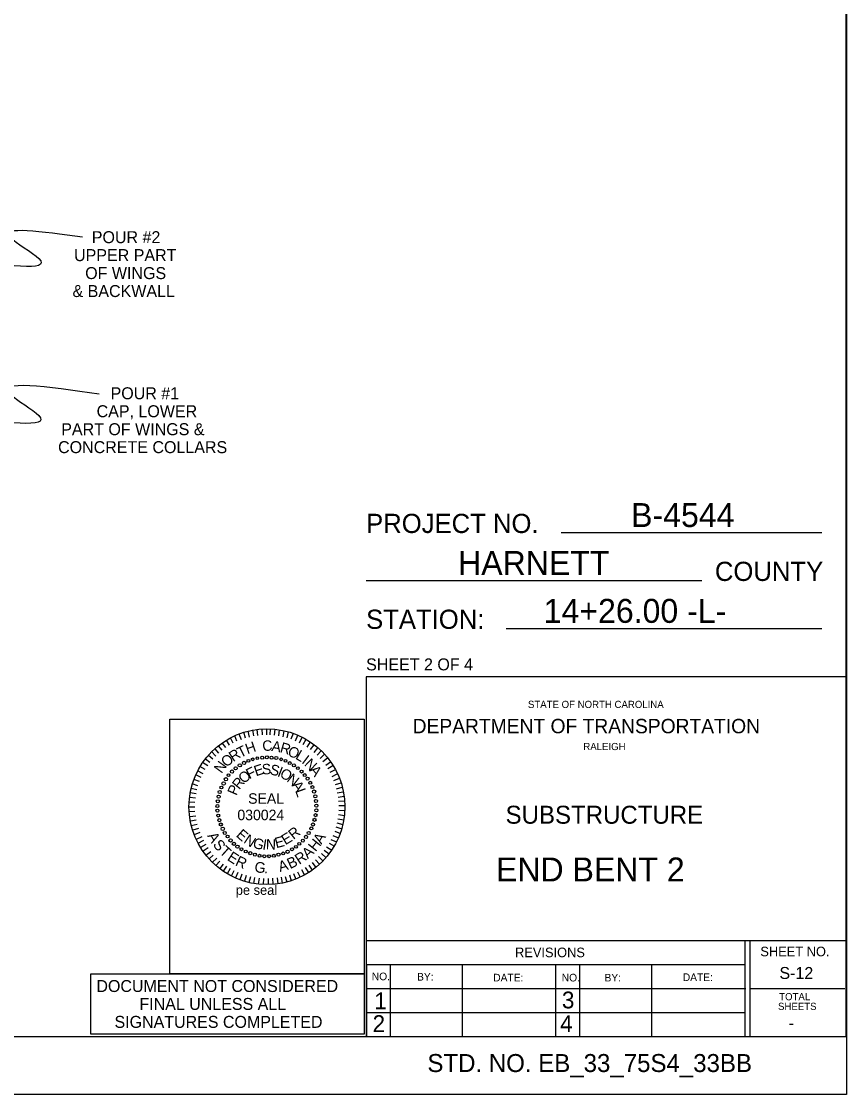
# Model space of a CAD drawing. Extents: x -41 to 191, y -168 to 6.
# Drawn here: x 171.73 to 191.43, y -50.47 to -24.84 of the extents above; entities that cross this region are included whole.
import ezdxf

# ---------------------------------------------------------------- set-up
doc = ezdxf.new("R2010")
doc.units = 0
for name, color, linetype in [('Dimension Lines', 7, 'Continuous'), ('Peseal', 7, 'Continuous'), ('Plan Sheet CELL', 7, 'Continuous'), ('Plot Shape CELL', 7, 'Continuous'), ('Sheet Sticker Exception Certification CELL', 7, 'Continuous'), ('Subtitle Text', 7, 'Continuous'), ('Text', 7, 'Continuous'), ('Title Text', 7, 'Continuous'), ('User Information Notes', 7, 'Continuous'), ('User Information Notes CELL', 7, 'Continuous')]:
    doc.layers.add(name, color=color, linetype=linetype)

msp = doc.modelspace()

# ---------------------------------------------------------------- linework, layer by layer
at = {"layer": 'Dimension Lines'}
for points in [[(173.186, -29.991), (171.467, -29.991), (172.144, -30.499), (170.147, -30.499)], [(173.587, -33.741), (171.467, -33.741), (172.144, -34.249), (170.147, -34.249)]]:
    msp.add_spline(points, degree=3, dxfattribs=at)
at = {"layer": 'Peseal'}
for p, q in [((177.277, -41.903), (177.251, -41.76)), ((177.376, -41.894), (177.358, -41.751)), ((177.483, -41.876), (177.474, -41.733)), ((177.591, -41.876), (177.591, -41.733)), ((177.671, -41.876), (177.68, -41.733)), ((177.769, -41.885), (177.787, -41.742)), ((177.877, -41.903), (177.895, -41.76)), ((176.696, -42.126), (176.624, -42.001)), ((176.785, -42.073), (176.723, -41.947)), ((176.875, -42.028), (176.821, -41.903)), ((176.982, -41.992), (176.929, -41.858)), ((177.081, -41.956), (177.036, -41.813)), ((177.179, -41.93), (177.143, -41.786)), ((177.975, -41.921), (178.002, -41.777)), ((178.074, -41.947), (178.109, -41.804)), ((178.172, -41.974), (178.226, -41.84)), ((178.27, -42.019), (178.333, -41.885)), ((178.369, -42.064), (178.431, -41.93)), ((178.458, -42.108), (178.53, -41.983)), ((176.374, -42.386), (176.267, -42.278)), ((176.446, -42.314), (176.356, -42.207)), ((176.526, -42.243), (176.437, -42.135)), ((176.607, -42.18), (176.526, -42.064)), ((178.548, -42.171), (178.628, -42.046)), ((178.628, -42.225), (178.718, -42.117)), ((178.718, -42.296), (178.807, -42.189)), ((178.789, -42.359), (178.888, -42.261)), ((176.177, -42.618), (176.052, -42.538)), ((176.231, -42.538), (176.124, -42.457)), ((176.302, -42.457), (176.195, -42.368)), ((178.861, -42.439), (178.968, -42.341)), ((178.923, -42.511), (179.04, -42.422)), ((178.995, -42.6), (179.111, -42.52)), ((176.07, -42.806), (175.936, -42.735)), ((176.115, -42.708), (175.989, -42.636)), ((179.049, -42.681), (179.165, -42.609)), ((179.102, -42.77), (179.228, -42.708)), ((175.945, -43.092), (175.81, -43.048)), ((175.98, -42.994), (175.846, -42.94)), ((176.025, -42.896), (175.891, -42.833)), ((179.147, -42.869), (179.272, -42.806)), ((179.192, -42.967), (179.326, -42.914)), ((179.228, -43.066), (179.362, -43.021)), ((175.9, -43.289), (175.757, -43.262)), ((175.918, -43.191), (175.784, -43.155)), ((179.254, -43.164), (179.389, -43.128)), ((179.272, -43.262), (179.415, -43.236)), ((175.873, -43.495), (175.73, -43.486)), ((175.882, -43.388), (175.748, -43.37)), ((179.29, -43.361), (179.433, -43.343)), ((179.299, -43.459), (179.442, -43.45)), ((175.873, -43.602), (175.73, -43.602)), ((175.873, -43.71), (175.73, -43.719)), ((175.891, -43.817), (175.748, -43.835)), ((179.299, -43.781), (179.442, -43.799)), ((179.308, -43.567), (179.451, -43.567)), ((179.308, -43.674), (179.451, -43.683)), ((175.9, -43.915), (175.766, -43.942)), ((175.927, -44.014), (175.784, -44.05)), ((179.236, -44.076), (179.38, -44.121)), ((179.263, -43.978), (179.406, -44.014)), ((179.281, -43.88), (179.424, -43.906)), ((175.954, -44.112), (175.819, -44.157)), ((175.989, -44.211), (175.855, -44.264)), ((176.034, -44.309), (175.9, -44.372)), ((179.165, -44.282), (179.299, -44.336)), ((179.21, -44.175), (179.344, -44.229)), ((176.079, -44.398), (175.945, -44.47)), ((176.132, -44.497), (176.007, -44.568)), ((176.186, -44.577), (176.07, -44.658)), ((179.013, -44.551), (179.138, -44.631)), ((179.075, -44.461), (179.201, -44.533)), ((179.12, -44.372), (179.254, -44.434)), ((176.249, -44.667), (176.132, -44.756)), ((176.311, -44.747), (176.213, -44.837)), ((176.392, -44.819), (176.285, -44.926)), ((178.825, -44.783), (178.932, -44.89)), ((178.897, -44.712), (179.004, -44.81)), ((178.959, -44.631), (179.075, -44.721)), ((176.463, -44.89), (176.374, -44.998)), ((176.544, -44.962), (176.463, -45.069)), ((176.624, -45.016), (176.544, -45.132)), ((176.714, -45.069), (176.642, -45.195)), ((178.414, -45.096), (178.485, -45.23)), ((178.503, -45.043), (178.583, -45.168)), ((178.592, -44.989), (178.673, -45.105)), ((178.673, -44.926), (178.762, -45.043)), ((178.753, -44.864), (178.843, -44.962)), ((176.803, -45.123), (176.741, -45.248)), ((176.893, -45.168), (176.839, -45.293)), ((176.991, -45.204), (176.946, -45.338)), ((177.099, -45.239), (177.054, -45.374)), ((177.197, -45.266), (177.161, -45.4)), ((177.295, -45.284), (177.269, -45.427)), ((177.403, -45.302), (177.385, -45.445)), ((177.51, -45.311), (177.501, -45.454)), ((177.617, -45.311), (177.617, -45.454)), ((177.725, -45.302), (177.734, -45.445)), ((177.832, -45.293), (177.85, -45.436)), ((177.93, -45.275), (177.957, -45.418)), ((178.029, -45.257), (178.065, -45.391)), ((178.127, -45.221), (178.172, -45.365)), ((178.226, -45.186), (178.279, -45.32)), ((178.324, -45.15), (178.387, -45.275))]:
    msp.add_line(p, q, dxfattribs=at)
for centre, radius in [((177.045, -42.547), 0.04), ((177.148, -42.498), 0.0341), ((177.251, -42.462), 0.0326), ((177.362, -42.435), 0.0316), ((177.479, -42.422), 0.0361), ((177.591, -42.413), 0.0358), ((177.702, -42.422), 0.0361), ((177.814, -42.431), 0.0369), ((177.93, -42.462), 0.0326), ((178.033, -42.498), 0.0341), ((178.136, -42.551), 0.0361), ((176.759, -42.753), 0.038), ((176.844, -42.677), 0.0385), ((176.942, -42.605), 0.0385), ((178.235, -42.605), 0.0361), ((178.329, -42.672), 0.0349), ((178.418, -42.753), 0.0349), ((176.557, -43.039), 0.0412), ((176.611, -42.936), 0.0385), ((176.674, -42.838), 0.0316), ((178.494, -42.838), 0.0349), ((178.561, -42.923), 0.0361), ((178.624, -43.021), 0.0361), ((176.463, -43.24), 0.0382), ((176.504, -43.133), 0.0341), ((178.677, -43.124), 0.0341), ((178.718, -43.231), 0.0382), ((178.745, -43.343), 0.0369), ((176.41, -43.576), 0.0358), ((176.419, -43.464), 0.0361), ((176.437, -43.352), 0.0369), ((178.762, -43.455), 0.0361), ((178.771, -43.567), 0.0358), ((176.41, -43.687), 0.0361), ((176.428, -43.804), 0.0361), ((178.753, -43.795), 0.0361), ((178.771, -43.678), 0.0361), ((176.454, -43.915), 0.0369), ((176.49, -44.018), 0.0382), ((178.651, -44.112), 0.0361), ((178.691, -44.018), 0.0382), ((178.727, -43.906), 0.0369), ((176.535, -44.121), 0.04), ((176.584, -44.22), 0.0361), ((176.651, -44.305), 0.0349), ((178.525, -44.314), 0.0385), ((178.588, -44.22), 0.0361), ((176.723, -44.398), 0.038), ((176.803, -44.479), 0.038), ((176.888, -44.546), 0.0385), ((176.982, -44.609), 0.0361), ((178.19, -44.609), 0.0361), ((178.284, -44.551), 0.0349), ((178.364, -44.479), 0.0349), ((178.449, -44.403), 0.0349), ((177.085, -44.662), 0.0341), ((177.192, -44.703), 0.0382), ((177.304, -44.738), 0.0369), ((177.416, -44.765), 0.0361), ((177.528, -44.774), 0.0358), ((177.644, -44.774), 0.0358), ((177.756, -44.765), 0.0361), ((177.868, -44.738), 0.0369), ((177.98, -44.707), 0.0341), ((178.083, -44.667), 0.04)]:
    msp.add_circle(centre, radius, dxfattribs=at)
at = {"layer": 'Plan Sheet CELL'}
for p, q in [((191.409, -0.989), (191.409, -49.079)), ((190.837, -37.056), (184.615, -37.056)), ((187.974, -38.201), (179.959, -38.201)), ((190.837, -39.345), (183.303, -39.345)), ((191.409, -40.49), (179.959, -40.49)), ((179.959, -40.49), (179.959, -49.079)), ((179.959, -46.788), (191.409, -46.788)), ((189.005, -46.788), (189.005, -49.079)), ((189.12, -46.788), (189.12, -49.079)), ((179.959, -47.36), (189.01, -47.36)), ((179.966, -47.36), (179.966, -49.079)), ((180.531, -47.36), (180.531, -49.079)), ((182.249, -47.37), (182.249, -49.087)), ((184.484, -47.36), (184.484, -49.093)), ((185.057, -47.36), (185.057, -49.08)), ((186.775, -47.36), (186.775, -49.08)), ((179.959, -47.933), (189.028, -47.933)), ((189.12, -47.933), (191.389, -47.933)), ((179.959, -48.505), (189.01, -48.505)), ((118.128, -49.079), (191.409, -49.079)), ((191.429, -50.467), (191.429, -50.467))]:
    msp.add_line(p, q, dxfattribs=at)
at = {"layer": 'Plot Shape CELL'}
msp.add_lwpolyline([(115.715, -0.087), (191.429, -0.087), (191.429, -50.467), (115.715, -50.467)], close=True, dxfattribs=at)
at = {"layer": 'Sheet Sticker Exception Certification CELL'}
msp.add_lwpolyline([(173.386, -47.586), (179.909, -47.586), (179.909, -49.021), (173.386, -49.021)], close=True, dxfattribs=at)
at = {"layer": 'User Information Notes'}
msp.add_line((177.591, -43.593), (177.591, -43.593), dxfattribs=at)
at = {"layer": 'User Information Notes CELL'}
msp.add_line((177.591, -43.593), (177.591, -43.593), dxfattribs=at)
msp.add_lwpolyline([(175.272, -41.504), (179.909, -41.504), (179.909, -47.586), (175.272, -47.586)], close=True, dxfattribs=at)
msp.add_circle((177.591, -43.593), 1.861, dxfattribs=at)

# ---------------------------------------------------------------- texts
at = {"layer": 'Peseal'}
for s, height, rotation, p in [('C', 0.25, 4.8625, (177.492, -42.269)), ('A', 0.25, 350.8088, (177.689, -42.261)), ('R', 0.25, 32.9699, (176.785, -42.529)), ('T', 0.25, 25.943, (176.955, -42.431)), ('H', 0.25, 18.9162, (177.125, -42.341)), ('R', 0.25, 343.7819, (177.886, -42.287)), ('O', 0.25, 336.7551, (178.065, -42.359)), ('L', 0.25, 329.7282, (178.253, -42.439)), ('N', 0.25, 54.0504, (176.508, -42.815)), ('O', 0.25, 39.9967, (176.624, -42.663)), ('I', 0.25, 322.7014, (178.405, -42.538)), ('N', 0.25, 315.6745, (178.467, -42.592)), ('O', 0.25, 42.5436, (177.045, -43.057)), ('F', 0.25, 26.4777, (177.17, -42.94)), ('E', 0.25, 18.4448, (177.331, -42.869)), ('S', 0.25, 2.3789, (177.474, -42.824)), ('S', 0.25, 346.313, (177.644, -42.815)), ('I', 0.25, 338.28, (177.823, -42.86)), ('O', 0.25, 330.2471, (177.877, -42.869)), ('N', 0.25, 322.2141, (178.047, -42.976)), ('A', 0.25, 308.6477, (178.592, -42.726)), ('R', 0.25, 50.5765, (176.929, -43.2)), ('A', 0.25, 306.1483, (178.172, -43.084)), ('P', 0.25, 66.6424, (176.866, -43.343)), ('L', 0.25, 290.0824, (178.261, -43.209)), ('A', 0.254, 300.3993, (176.16, -44.288)), ('E', 0.25, 318.5179, (176.839, -44.291)), ('N', 0.25, 326.5361, (177.018, -44.443)), ('E', 0.25, 14.6452, (177.814, -44.586)), ('E', 0.25, 30.6815, (178.029, -44.515)), ('R', 0.25, 38.6997, (178.226, -44.39)), ('A', 0.254, 59.6007, (178.895, -44.503)), ('S', 0.254, 309.4349, (176.287, -44.504)), ('T', 0.254, 318.1096, (176.439, -44.69)), ('G', 0.25, 342.5725, (177.233, -44.56)), ('I', 0.25, 350.5906, (177.474, -44.613)), ('N', 0.25, 358.6088, (177.564, -44.613)), ('A', 0.254, 42.3241, (178.566, -44.85)), ('H', 0.254, 51.3597, (178.751, -44.681)), ('E', 0.254, 327.1453, (176.625, -44.857)), ('R', 0.254, 335.458, (176.818, -44.984)), ('B', 0.254, 24.8312, (178.143, -45.085)), ('R', 0.254, 33.5776, (178.363, -44.983)), ('G', 0.254, 353.3858, (177.284, -45.154)), ('A', 0.254, 15.7955, (177.902, -45.153)), ('.', 0.254, 2.1323, (177.525, -45.182))]:
    msp.add_text(s, height=height, rotation=rotation, dxfattribs=at).set_placement(p)
for s, p in [('SEAL', (177.143, -43.522)), ('030024', (176.886, -43.915))]:
    msp.add_text(s, height=0.2505, dxfattribs=at).set_placement(p)
at = {"layer": 'Plan Sheet CELL'}
for s, height, p in [('PROJECT NO.', 0.458, (179.959, -37.056)), ('COUNTY', 0.458, (188.286, -38.201)), ('STATION:', 0.458, (179.959, -39.345)), ('SHEET 2 OF 4', 0.28625, (179.959, -40.337)), ('STATE OF NORTH CAROLINA', 0.17174, (183.823, -41.235)), ('DEPARTMENT OF TRANSPORTATION', 0.34349, (181.07, -41.839)), ('RALEIGH', 0.1717, (185.145, -42.241)), ('REVISIONS', 0.229, (183.515, -47.187)), ('SHEET NO.', 0.229, (189.372, -47.165)), ('NO.', 0.1825, (180.095, -47.737)), ('BY:', 0.1825, (181.176, -47.746)), ('DATE:', 0.1825, (182.995, -47.766)), ('NO.', 0.1825, (184.63, -47.766)), ('BY:', 0.1825, (185.652, -47.767)), ('DATE:', 0.1825, (187.52, -47.756)), ('1', 0.401, (180.155, -48.428)), ('3', 0.401, (184.634, -48.409)), ('TOTAL', 0.1717, (189.821, -48.215)), ('SHEETS', 0.1717, (189.794, -48.447)), ('2', 0.401, (180.114, -48.973)), ('4', 0.401, (184.591, -48.973))]:
    msp.add_text(s, height=height, dxfattribs=at).set_placement(p)
at = {"layer": 'Sheet Sticker Exception Certification CELL'}
for s, p in [('DOCUMENT NOT CONSIDERED', (173.52, -48.018)), ('FINAL UNLESS ALL', (174.547, -48.446)), ('SIGNATURES COMPLETED', (173.952, -48.874))]:
    msp.add_text(s, height=0.28561, dxfattribs=at).set_placement(p)
at = {"layer": 'Subtitle Text'}
for s, p in [('SUBSTRUCTURE', (183.289, -43.999)), ('STD. NO. EB_33_75S4_33BB', (181.423, -49.929))]:
    msp.add_text(s, height=0.429, dxfattribs=at).set_placement(p)
at = {"layer": 'Text'}
for s, p in [('POUR #2', (173.41, -30.134)), ('UPPER PART', (172.987, -30.563)), ('OF WINGS', (173.252, -30.992)), ('& BACKWALL', (172.95, -31.421)), ('POUR #1', (173.858, -33.862)), ('CAP, LOWER', (173.525, -34.291)), ('PART OF WINGS &', (172.68, -34.72)), ('CONCRETE COLLARS', (172.605, -35.149)), ('S-12', (189.827, -47.707)), ('-', (190.046, -48.903))]:
    msp.add_text(s, height=0.286, dxfattribs=at).set_placement(p)
at = {"layer": 'Title Text'}
for s, p in [('B-4544', (186.287, -36.913)), ('HARNETT', (182.156, -38.058)), ('14+26.00 -L-', (184.199, -39.202)), ('END BENT 2', (183.06, -45.378))]:
    msp.add_text(s, height=0.572, dxfattribs=at).set_placement(p)
at = {"layer": 'User Information Notes CELL'}
msp.add_text('pe seal', height=0.229, dxfattribs=at).set_placement((176.848, -45.698))

doc.saveas('drawing.dxf')
